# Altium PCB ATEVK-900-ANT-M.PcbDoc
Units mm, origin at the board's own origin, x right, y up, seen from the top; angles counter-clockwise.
Board outline 20.32 x 32.84 mm, 2 copper layers (Top Layer, Bottom Layer); 5 components, 3 nets, 9 pads, 47 vias.
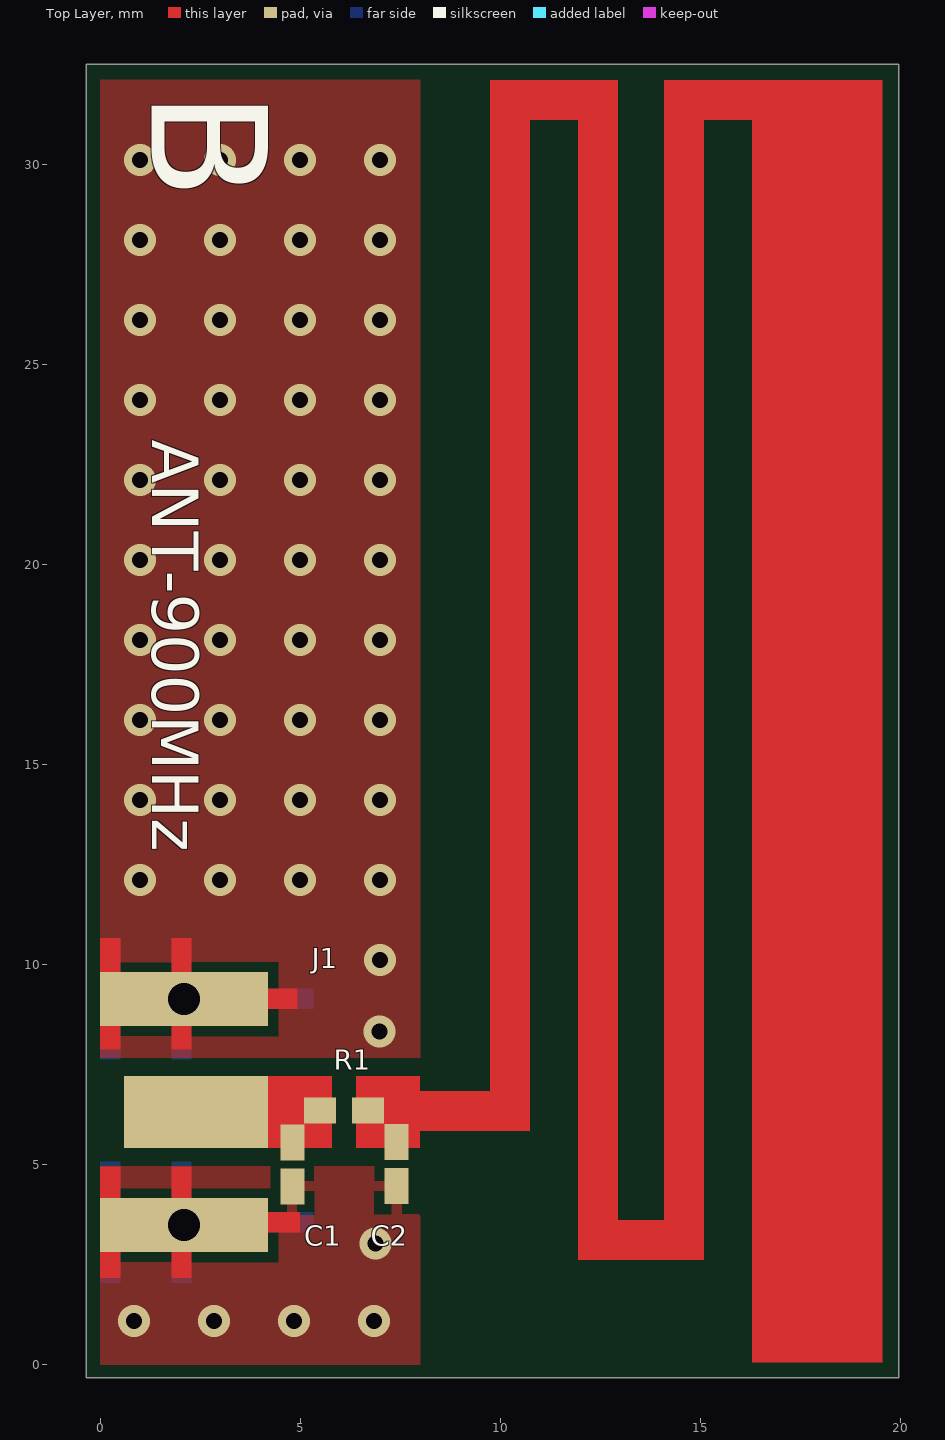
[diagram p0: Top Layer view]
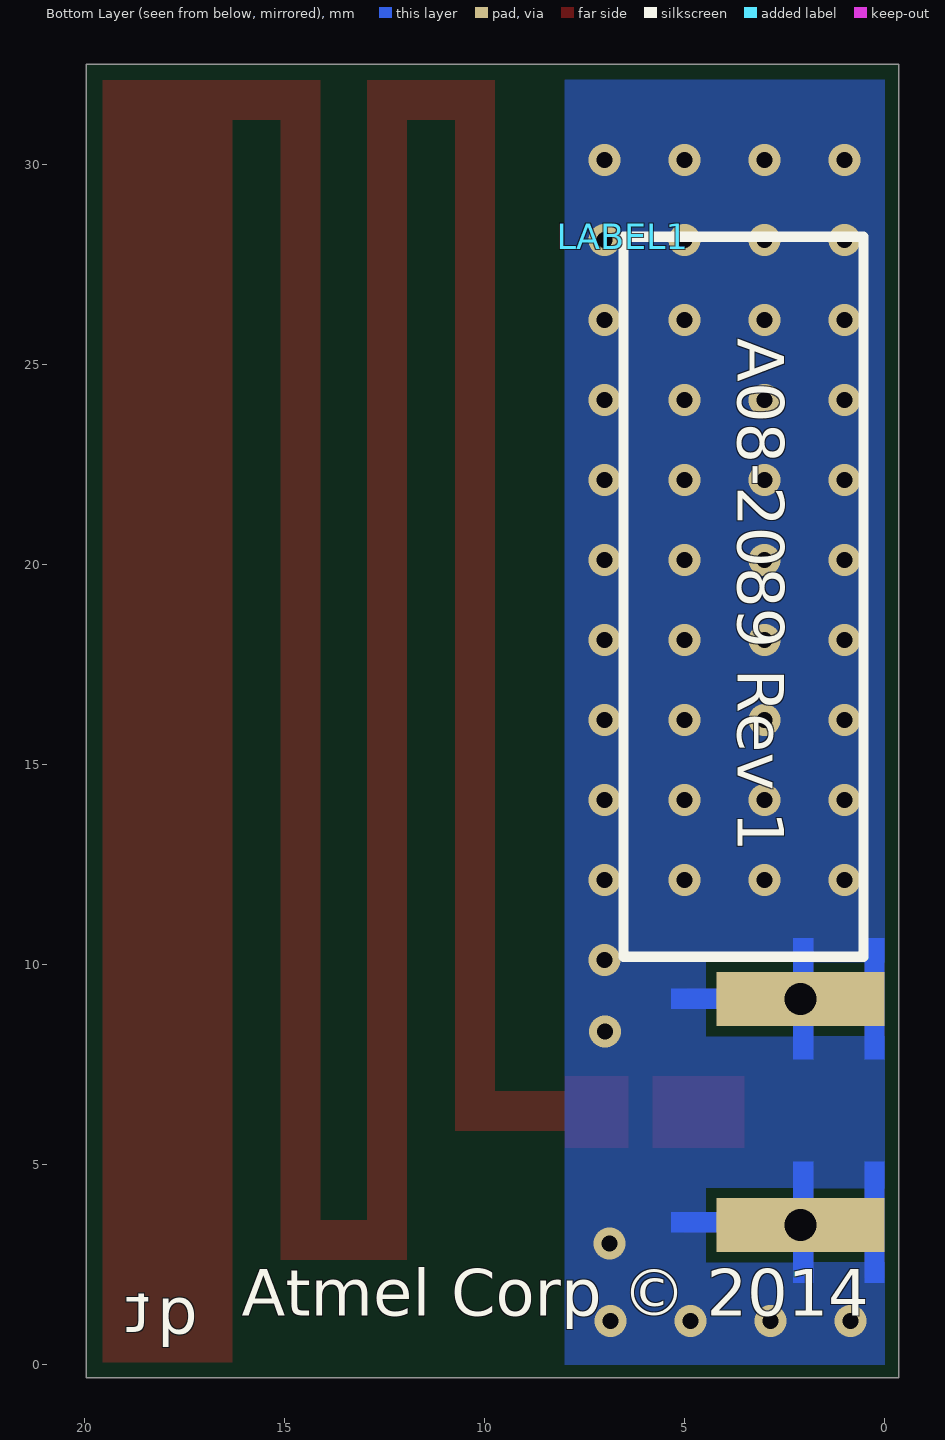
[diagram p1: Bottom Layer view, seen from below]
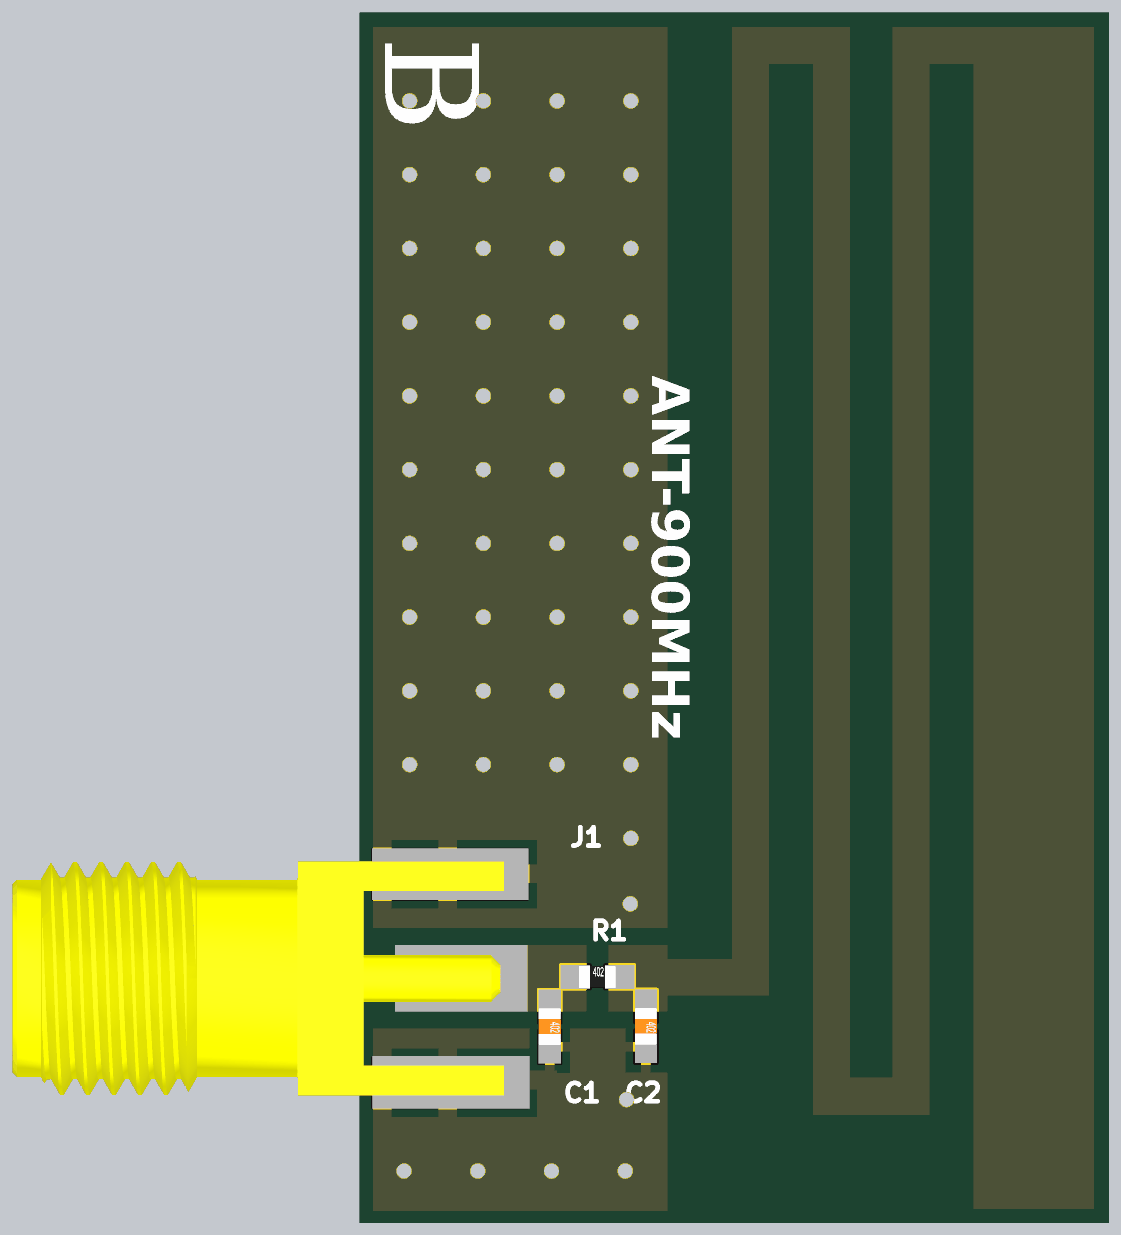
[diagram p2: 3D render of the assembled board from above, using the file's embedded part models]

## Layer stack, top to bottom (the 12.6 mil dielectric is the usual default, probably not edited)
Top Layer: signal copper 0.0356
Dielectric: core 0.32, FR-4, Dk 4.8
Bottom Layer: signal copper 0.0356

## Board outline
-0.356,-0.33 19.964,-0.33 19.964,32.512 -0.356,32.512

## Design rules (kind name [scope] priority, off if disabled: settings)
Clearance [All] p1: gap=0.254
PolygonConnect PolygonConnect_pad [isPad] p1: connectstyle=Relief reliefconductorwidth=0.254 reliefentries=4 polygonreliefangle="90 Angle" airgapwidth=0.254
PolygonConnect PolygonConnect_via [isVia] p2: connectstyle=Direct reliefconductorwidth=0.254 reliefentries=4 polygonreliefangle="90 Angle" airgapwidth=0.254
PolygonConnect [All] p3: connectstyle=Direct reliefconductorwidth=0.254 reliefentries=4 polygonreliefangle="90 Angle" airgapwidth=0.254
RoutingVias [All] p1: holewidth=0.4 width=0.8 viastyle="Through Hole" minholewidth=0.4 minwidth=0.8 maxholewidth=0.4 maxwidth=0.8
SilkscreenOverComponentPads [All] p1: minsilkscreentomaskgap=0.254
SolderMaskExpansion [All] p1: expansion=0.05
Width [All] p1: maxlimit=0.254 minlimit=0.254 preferedwidth=0.254
27 further rules are at their usual default settings.

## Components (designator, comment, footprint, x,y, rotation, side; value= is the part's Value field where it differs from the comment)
C1 "CAP-NONPOL" AP1-00001 4.801,5.004 r270 top
C2 "CAP-NONPOL" AP1-00001 7.408,5.008 r270 top
J1 "Board Edge Mounting" AP8-00443 2.4,6.308 r0 top
LABEL1 "PCBA_LABEL" AP8-00317 6.528,28.194 r270 bottom
R1 "R2" AP2-00000 6.096,6.35 r0 top

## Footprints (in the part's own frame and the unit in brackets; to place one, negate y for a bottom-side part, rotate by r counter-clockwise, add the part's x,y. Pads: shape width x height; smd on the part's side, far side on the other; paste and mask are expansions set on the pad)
AP1-00001 [mm] "Standard 0402 SMD capacitor footprint"
  rect 0.9x0.6 smd: 1(-0.55,0) 2(0.55,0)
  body extent -0.5,-0.3 0.5,0.3, height 0.2
AP2-00000 [mm] "Standard 0402 SMD resistor footprint"
  rect 0.8x0.65 smd: 1(-0.6,0) 2(0.6,0)
  body extent -0.5,-0.3 0.5,0.3, height 0.2
AP8-00317 [mm] "Placement area for 18x6mm sticker"
  silkscreen extent 0,0 18,6
AP8-00443 [mm] "SMA card edge mount 1.6mm substrate"
  rect 3.6x1.8 smd paste-0.9 mask+0: 1(0,0)
  rect 4.2x1.35 hole 0.8 paste-0.3: 2(-0.3,-2.825) 2.1(-0.3,2.825)
  body extent -12.17,-3.18 1.16,3.18, height 3.71

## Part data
C1 C2: library part A01-0015, "Ceramic capacitor, SMD 0402, NP0, 50V, +/-5%"
J1: library part A08-1047, "End Launch Jack Receptacle, Round Contact (de21535)"
LABEL1: library part A09-0611, "PCBA identification label PP Top White Gloss"
R1: library part A02-0163, "RES 0.0 OHM 1/16W 0402 SMD"

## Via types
v1: diameter 0.8, hole 0.4, Top Layer to Bottom Layer, tented both sides, 47 vias

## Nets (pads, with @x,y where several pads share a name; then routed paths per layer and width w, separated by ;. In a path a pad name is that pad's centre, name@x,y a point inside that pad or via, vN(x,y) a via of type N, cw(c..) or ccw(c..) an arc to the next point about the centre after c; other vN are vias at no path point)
GND: C1.2 C2.2 J1.2 J1.2.1
  other v1: 0.848,1.085 2.848,1.085 4.848,1.085 6.848,1.085 6.883,3.023 6.985,8.331 7,10.108 1,12.108 3,12.108 5,12.108 7,12.108 1,14.108 3,14.108 5,14.108 7,14.108 1,16.108 3,16.108 5,16.108 7,16.108 1,18.108 3,18.108 5,18.108 7,18.108 1,20.108 3,20.108 5,20.108 7,20.108 1,22.108 3,22.108 5,22.108 7,22.108 1,24.108 3,24.108 5,24.108 7,24.108 1,26.108 3,26.108 5,26.108 7,26.108 1,28.108 3,28.108 5,28.108 7,28.108 1,30.108 3,30.108 5,30.108 7,30.108
NetA1_1: C2.1 R1.2
NetC1_1: C1.1 J1.1 R1.1

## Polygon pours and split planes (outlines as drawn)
GND on Top Layer "Top Layer-No Net" (solid, pour order 8): 0,4.953 8,4.953 8,0 0,0
GND on Top Layer "Top Layer-No Net" (solid, pour order 7): 0,32.115 0,7.671 8,7.671 8,32.115
GND on Bottom Layer "Top Layer-No Net" (solid, pour order 5): 0,0 0,32.115 8,32.115 8,0

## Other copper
Top Layer:
  region net GND: 5,3.302 5,3.81 2.206,3.81 2.206,3.302
  rectangle net GND: 1.778,2.159 2.286,4.953
  region net GND: 4.927,8.89 4.927,9.398 2.133,9.398 2.133,8.89
  rectangle net GND: 1.778,7.874 2.286,10.668
  rectangle net GND: 0,2.159 0.508,4.953
  rectangle net GND: 0,7.874 0.508,10.668
  rectangle net NetA1_1: 14.122,31.115 17.272,32.115
  rectangle net NetA1_1: 11.963,2.608 14.934,3.616
  rectangle net NetA1_1: 9.779,31.115 12.929,32.115
  region net NetA1_1: 19.558,0.051 19.558,32.115 16.3,32.115 16.3,0.051
  region net NetA1_1: 15.1,2.608 15.1,32.115 14.1,32.115 14.1,2.608
  region net NetA1_1: 12.944,2.608 12.944,32.115 11.945,32.115 11.945,2.608
  region net NetA1_1: 10.744,5.867 10.744,32.115 9.745,32.115 9.745,5.867
  rectangle net NetA1_1: 6.4,5.41 8,7.214
  rectangle net NetA1_1: 7.976,5.842 10.744,6.842
  rectangle net NetC1_1: 3.5,5.41 5.8,7.209
Bottom Layer:
  rectangle net GND: 0,2.032 0.508,5.08
  rectangle net GND: 1.778,2.032 2.286,5.08
  rectangle net GND: 1.973,3.302 5.334,3.81
  rectangle net GND: 1.973,8.89 5.334,9.398
  rectangle net GND: 1.778,7.62 2.286,10.668
  rectangle net GND: 0,7.62 0.508,10.668

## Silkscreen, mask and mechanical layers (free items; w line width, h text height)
Top Overlay:
  text "B" at 0.33,31.852 h5 r270
  text "ANT-900MHz" at 0.914,23.114 h2 r270
Bottom Overlay:
  text "A08-2089 Rev 1" at 4.064,25.654 h2 r90
  text "Atmel Corp © 2014" at 16.067,0.832 h2
  text "t" at 18.364,0.432 h2
  text "p" at 18.186,0.381 h2
Top Paste:
  rectangle: -0.011,2.778 4.256,4.201
  rectangle: -0.021,8.436 4.221,9.833
  rectangle: 0.61,5.41 4.191,7.214
Bottom Paste:
  rectangle: -0.025,2.769 4.242,4.191
  rectangle: -0.025,8.433 4.216,9.83
Mechanical 1:
  the board outline again, w0.254
Mechanical 4:
  drawing of 169 lines, arcs and shapes, not listed
  text "( SEE NOTE 1A )" at -49.98,44.064 h1.78
  text "SOLDER LEVEL" at -75.533,44.014 h1.78
  text "COPPER PLATE" at -75.533,41.474 h1.78
  text "35 um" at -50.26,40.204 h1.78
  text "LAYER 1" at -108.807,38.934 h1.78
  text "COPPER FOIL" at -75.533,38.934 h1.78
  text "}" at -53.816,38.807 h4.44
  text "Core" at -74.898,18.655 h1.78
  text "( SEE NOTE 2A )" at -49.632,18.618 h1.78
  text "1530um" at -59.519,18.548 h1.78
  text "( SEE NOTE 3A )" at -122.619,17.737 h1.78
  text "LAYER 2" at -108.807,-2.976 h1.78
  text "COPPER FOIL" at -75.533,-2.976 h1.78
  text "35 um" at -50.26,-4.246 h1.78
  text "COPPER PLATE" at -75.533,-5.516 h1.78
  text "}" at -53.816,-5.643 h4.44
  text "( SEE NOTE 1A )" at -49.851,-7.936 h1.78
  text "SOLDER LEVEL" at -75.533,-8.056 h1.78
  text "NOTE :" at -93.612,-11.935 h1.78
  text "1A:  SURFACE PROTECTION: Chemical Gold" at -88.808,-15.911 h1.78
  text "2A:  DIELECTRIC FR4" at -89.104,-19.723 h1.78
  text "3A:  TOTAL THICKESS TO BE DEFINED BY MANUFACTURER" at -89.142,-23.823 h1.78
  text "WITH RESPECT TO STANDARD FINISHING" at -82.348,-27.589 h1.78
  text "THE BOARD MUST BE RoHS COMPLIANT" at -89.267,-32.755 h1.78
  text "DETAIL A ( CROSS-SECTION )" at -107.009,-45.61 h3.05
  text "SCALE = NONE" at -87.832,-50.182 h1.78
Drill Drawing:
  text ".legend" at -0.889,-22.784 h1.52

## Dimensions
-0.356,-0.381 to 19.964,-0.381 on Mechanical 13
20.015,-0.356 to 19.99,32.512 on Mechanical 13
